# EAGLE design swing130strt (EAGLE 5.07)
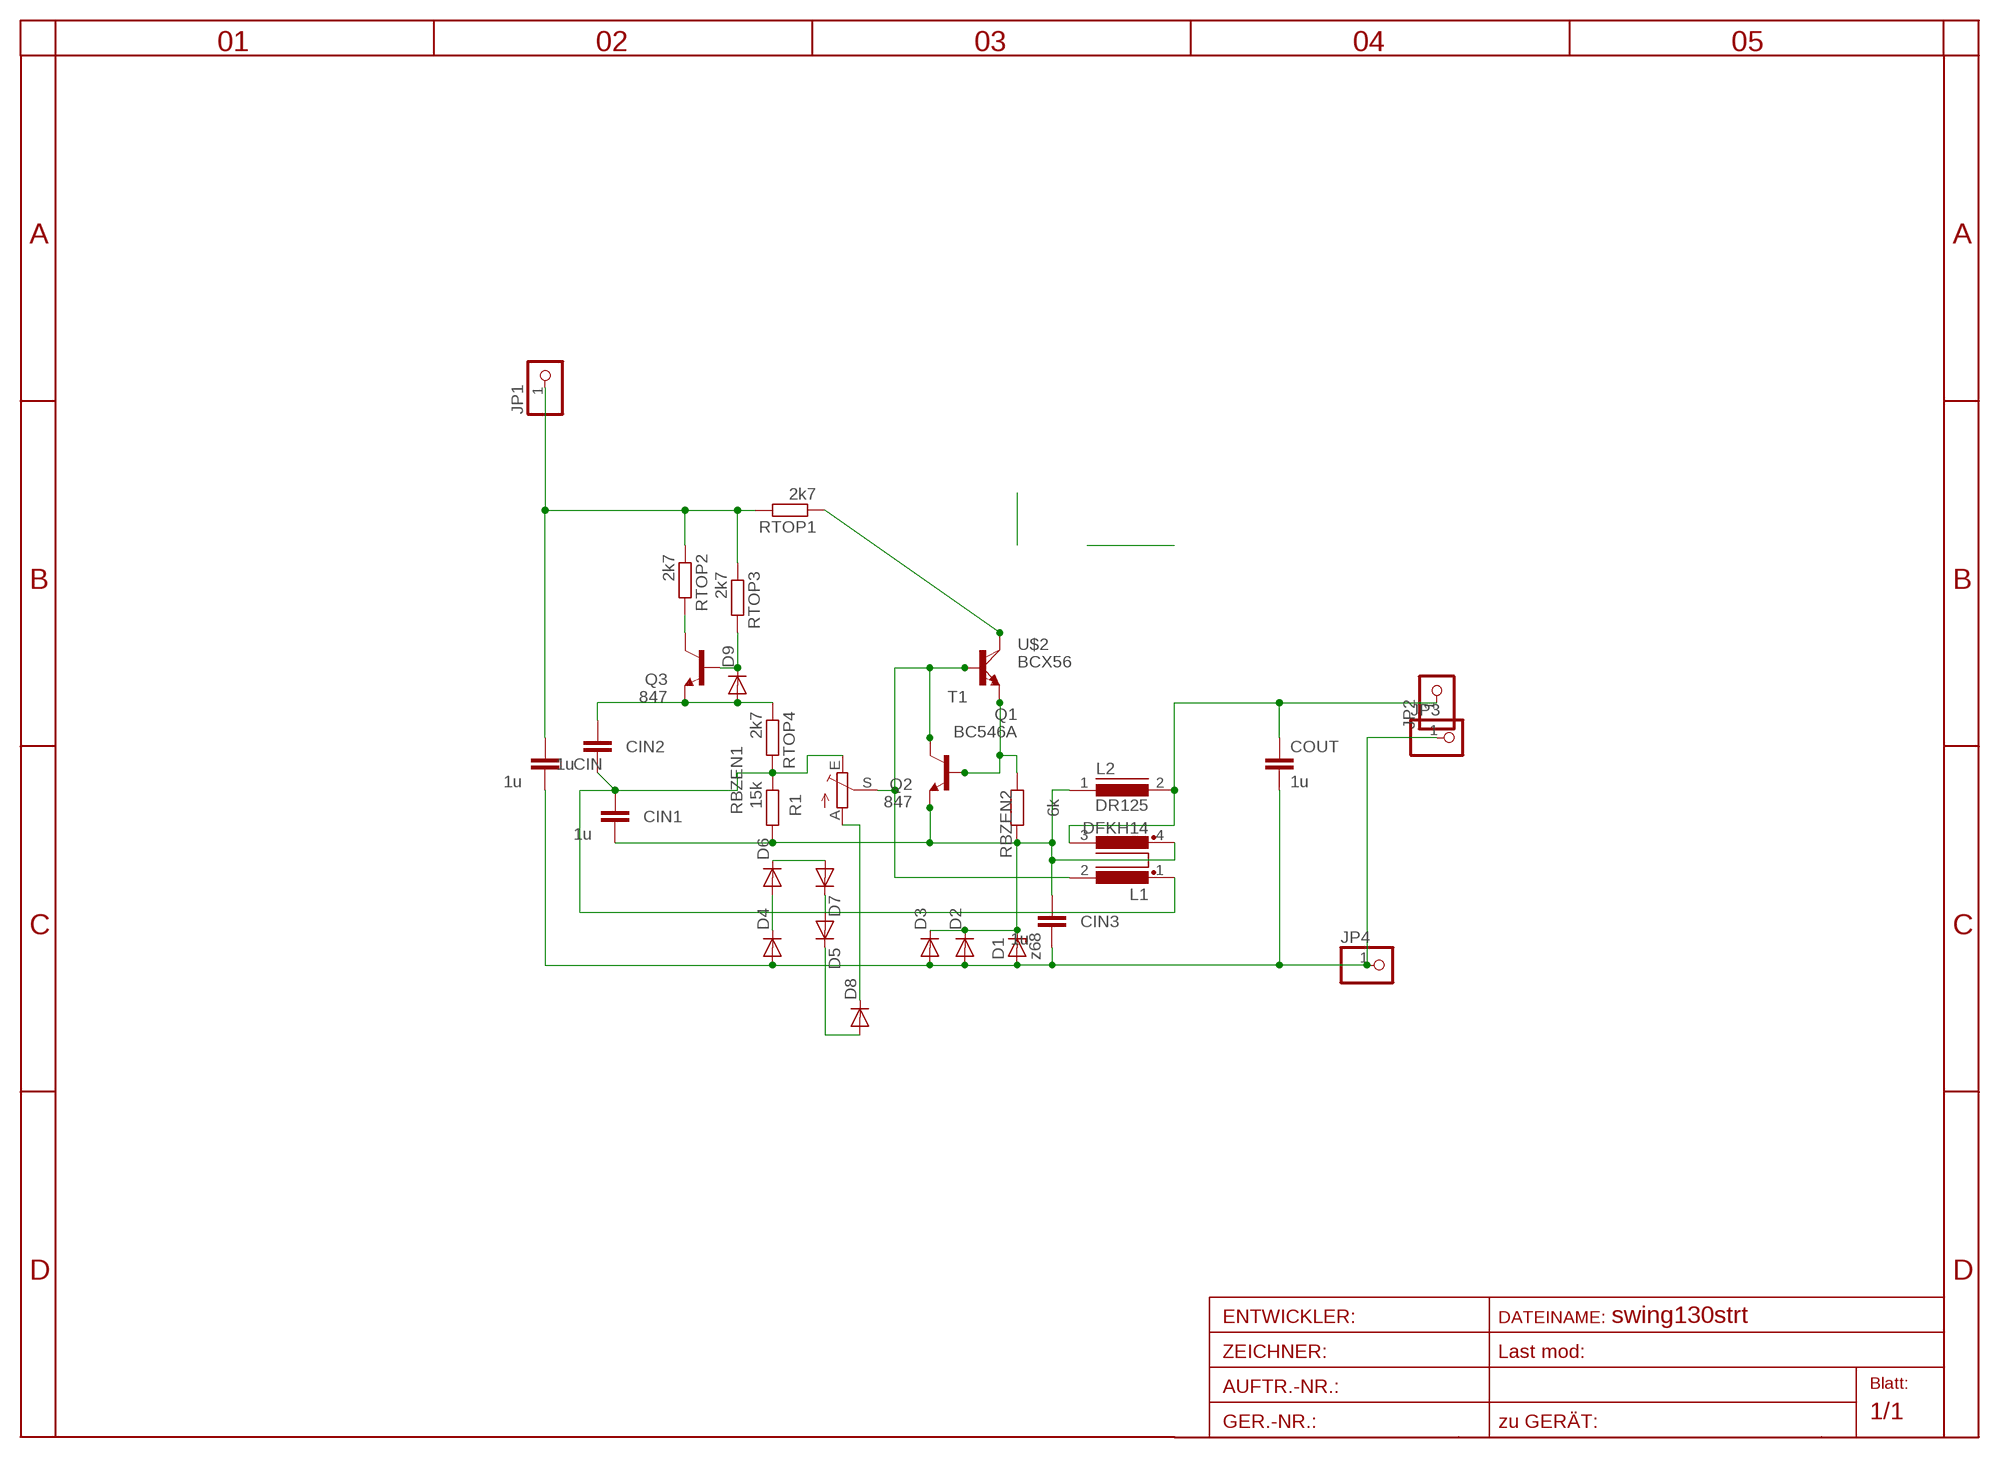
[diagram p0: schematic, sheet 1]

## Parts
CIN  1u  C-EU025-024X044  [C025-024X044]
CIN1  1u  C-EU025-024X044  [C025-024X044]
CIN2  1u  C-EU025-024X044  [C025-024X044]
CIN3  1u  C-EU025-024X044  [C025-024X044]
COUT  1u  C-EU025_050-055X075  [C025_050-055X075]
D1  z68  ZENER-DIODESOD80C  [SOD80C]
D2  DIODE-D-5  [D-5]
D3  DIODE-SMC  [SMC]
D4  DIODE-MINIMELF  [MINIMELF]
D5  DIODE-MINIMELF  [MINIMELF]
D6  DIODE-MINIMELF  [MINIMELF]
D7  DIODE-MINIMELF  [MINIMELF]
D8  DIODE-MINIMELF  [MINIMELF]
D9  DIODE-MINIMELF  [MINIMELF]
JP1  PINHD-1X11X0.4  [1X01]
JP2  PINHD-1X11X0.4  [1X01]
JP3  PINHD-1X11X0.4  [1X01]
JP4  PINHD-1X11X0.4  [1X01]
L1  DFKH14  [DFKH14]
L2  DR125  [DR125]
Q1  BC546A  [TO92-EBC]
Q2  847  BC847ASMD  [SOT23]
Q3  847  BC847ASMD  [SOT23]
R1  TRIM_EU-S64W  [S64W]
RBZEN1  15k  R-EU_0204/3  [0204/3]
RBZEN2  6k  R-EU_0207/10  [0207/10]
RTOP1  2k7  R-EU_0207/12  [0207/12]
RTOP2  2k7  R-EU_R0805  [R0805]
RTOP3  2k7  R-EU_R0805  [R0805]
RTOP4  2k7  R-EU_0204/5  [0204/5]
T1  -NPN-TO126V  [TO126V]
U$2  BCX56  [SOT223]

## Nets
C: RTOP1.1 T1.2(C) U$2.2(C)
CB: L1.2 Q1.C Q2.3(C) R1.S T1.3(B) U$2.1(B)
DB: CIN1.2 CIN3.1 D1.C D2.C D3.C L1.4 L2.1 Q1.E Q2.2(E) RBZEN1.2 RBZEN2.2
EE: Q1.B Q2.1(B) RBZEN2.1 T1.1(E) U$2.3(E)
GND: CIN3.2 CIN.2 COUT.2 D1.A D2.A D3.A D4.A JP3.1 JP4.1
MID: CIN1.1 CIN2.2 L1.1 R1.E RBZEN1.1 RTOP4.2
N$1: D4.C D6.A
N$2: D6.C D7.A
N$4: D5.A D7.C
N$5: D5.C D8.A
N$7: CIN2.1 D9.A Q3.2(E) RTOP4.1
N$8: D8.C R1.A
N$9: D9.C Q3.1(B) RTOP3.2
N$10: Q3.3(C) RTOP2.2
OUT: COUT.1 JP2.1 L1.3 L2.2
VPLUS: CIN.1 JP1.1 RTOP1.2 RTOP2.1 RTOP3.1

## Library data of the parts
CIN CIN1-CIN3 COUT = rcl:C-EU: CAPACITOR, European symbol
D1 = diode:ZENER-DIODE: Z-Diode
D2 = diode:DIODE-: DIODE
D3-D9 = diode-1:DIODE-: DIODE
JP1-JP4 = pinhead:PINHD-1X1: PIN HEADER
L1 = inductors:DFKH14: FILTER
L2 = inductors:DR125: High Power Density, High Efficiency, Shielded Inductors
Q1 = transistor-npn:BC546*: NPN Transistor
Q2 Q3 = transistor-npn:BC847*: NPN Transistor
R1 = pot-7:TRIM_EU-: POTENTIOMETER
RBZEN1 RBZEN2 RTOP1-RTOP4 = rcl:R-EU_: RESISTOR, European symbol
T1 = transistor:*-NPN-: NPN Transistror BF959 corrected 2008.03.06
U$2 = transistor-power:BCX56

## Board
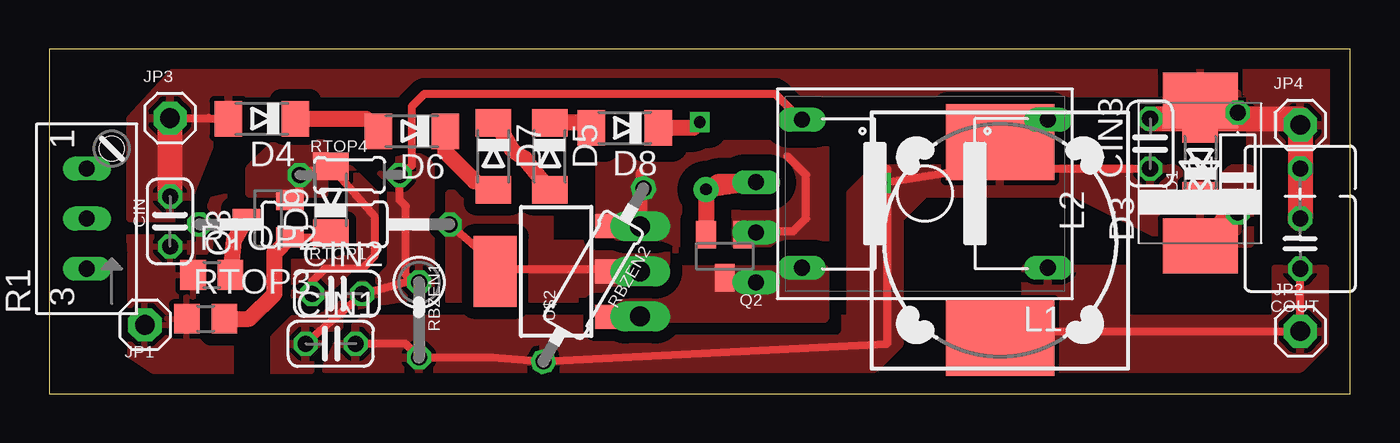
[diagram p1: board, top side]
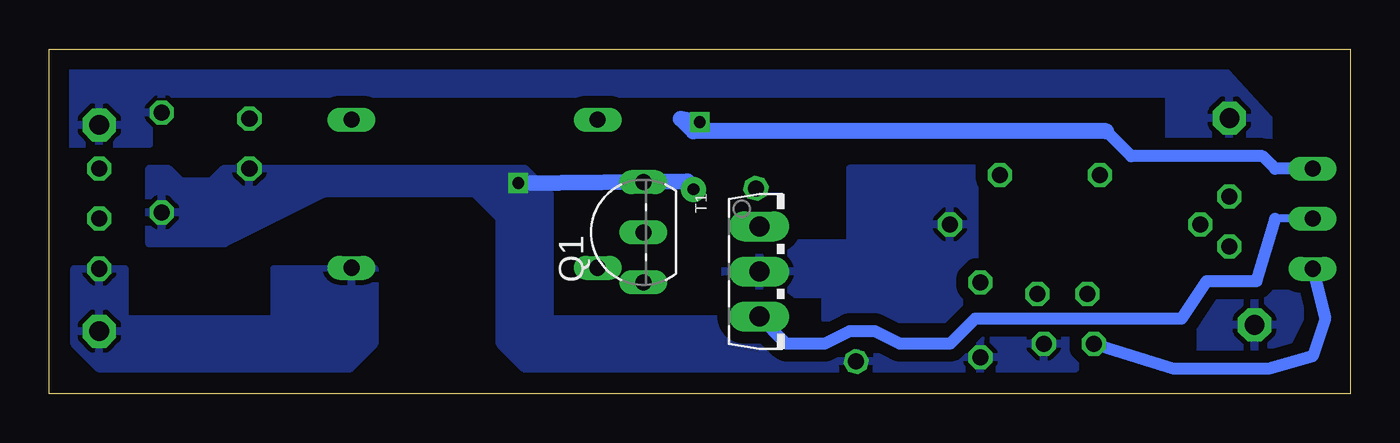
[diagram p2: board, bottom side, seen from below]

Size 66.04 x 17.5 mm. Coordinates in mm from the lower left corner, seen from the top.
Outline: 0,0 66.04,0 66.04,17.5 0,17.5 0,0
Copper layers (1*16): Top 0.035mm / dielectric 1.5mm / Bottom 0.035mm
Design rules "default *": minimum track width 10mil, minimum drill 20mil, track to track 8mil, track to pad 8mil, pad to pad 8mil, via to via 8mil, smd to smd 8mil, copper to edge 40mil, drill to drill 8mil, minimum pad ring 1mil, minimum via ring 8mil, stop-mask expansion 4mil, vias tented up to drill 0mil, thermal gap 10mil

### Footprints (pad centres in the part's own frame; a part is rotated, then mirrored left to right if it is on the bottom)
C025-024X044 = drill 0.813 octagon: 1 -1.27,0; 2 1.27,0
C025_050-055X075 = drill 0.813 octagon: 1 -1.27,0; 2 1.27,0; 3 3.81,0
SOD80C = smd 1.4 x 1.8: A 1.7,0; C -1.7,0
D-5 = drill 0.813 octagon: A 2.54,0; C -2.54,0
SMC = smd 2.8 x 3.8: A 3.7,0; C -3.7,0
MINIMELF = smd 1.4 x 1.8: A 1.7,0; C -1.7,0
1X01 = drill 1 pad 1.676 octagon: 1 0,0
DFKH14 = drill 0.813 long: 1 6.248,-3.759; 2 6.248,3.759; 3 -6.248,3.759; 4 -6.248,-3.759
DR125 = smd 3.85 x 5.5: 1 -4.975,0; 2 4.975,0
TO92-EBC = drill 0.813 long: B 0,-1.27; C -2.54,-1.27; E 2.54,-1.27
SOT23 = smd 1 x 1.4: 1 -0.95,-1.1; 2 0.95,-1.1; 3 0,1.1
S64W = drill 0.813 long: A 2.54,1.27; E -2.54,1.27; S 0,1.27
0204/3 = drill 0.813 octagon: 1 -1.27,0; 2 2.54,0
0207/10 = drill 0.813 octagon: 1 -5.08,0; 2 5.08,0
0207/12 = drill 0.813 octagon: 1 -6.35,0; 2 6.35,0
R0805 = smd 1.3 x 1.5: 1 -0.95,0; 2 0.95,0
0204/5 = drill 0.813 octagon: 1 -2.54,0; 2 2.54,0
TO126V = drill 1.016 long: 1 -2.286,-1.27; 2 0,-1.27; 3 2.286,-1.27
SOT223 = smd 1.219 x 2.235: 1 -2.311,-3.099; 2 0,-3.099; 3 2.311,-3.099 | smd 3.6 x 2.2: 4 0,3.099

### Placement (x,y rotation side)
CIN  6.13,8.75 90 top
CIN1  14.29,2.54 0 top
CIN2  14.61,5.08 0 top
CIN3  55.88,12.7 90 top
COUT  63.5,7.62 90 top
D1  58.42,11.75 90 top
D2  60.32,11.75 90 top
D3  58.42,11.2 90 top
D4  10.79,13.97 180 top
D5  25.4,12.06 270 top
D6  18.41,13.34 180 top
D7  22.54,12.06 270 top
D8  29.21,13.5 180 top
D9  14.29,9.84 90 top
JP1  4.86,3.5 0 top
JP2  63.5,3.17 0 top
JP3  6.13,14 0 top
JP4  63.5,13.65 0 top
L1  44.45,10.16 180 top
L2  48.26,7.8 270 top
Q1  37.15,8.2 90 bottom
Q2  34.29,6.99 180 top
Q3  11.11,8.89 90 top
R1  3.17,8.89 90 top
RBZEN1  18.77,4.38 270 top
RBZEN2  27.62,6.03 240 top
RTOP1  13.97,8.6 180 top
RTOP2  8.26,6.03 0 top
RTOP3  7.94,3.81 0 top
RTOP4  15.24,11.11 0 top
T1  28.73,6.21 270 bottom
U$2  25.73,6.21 90 top

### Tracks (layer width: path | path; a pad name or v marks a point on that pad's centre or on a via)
C
  Top 0.406: RTOP1.1 22.54,6.67 22.86,6.35 28.69,6.35 U$2.2 T1.2
  pour Bottom (isolate 0.61): 19.05,11.43 25.4,11.43 25.4,7.62 31.75,7.62 31.75,5.08 26.67,5.08 26.67,3.81 19.05,3.81
  pour Top (isolate 0.61, rank 4, no thermals): 20.32,10.16 25.4,10.16 25.4,7.62 31.75,7.62 31.75,5.08 26.67,5.08 26.67,3.81 20.32,3.81
CB
  Bottom 0.406: R1.S 3.81,8.89
  Bottom 0.61: 3.81,8.89 4.76,5.71 7.3,5.71 8.57,3.81 19.05,3.81 20.32,2.54 22.86,2.54 24.13,3.17 25.4,3.17 26.67,2.54 28.62,2.54 T1.3
  pour Top (isolate 0.61, rank 2, no thermals): 39.37,6.35 39.37,3.81 27.94,3.81 31.75,6.35
DB  (via drill 0.6, 0.6 pad 1.27)
  Top 0.406: 46.88,11.43 CIN3.1 | 46.88,11.43 L2.1 | CIN1.2 18.08,2.54 RBZEN1.2 22.48,1.84 RBZEN2.2 42.54,2.54 42.54,11.43 v42.23,10.7 46.88,11.43 | Q2.2
  Top 0.813: v33.34,10.38 Q1.E 33.92,10.74 33.34,10.16 Q2.2 | L2.1 49.55,12.77 L1.4 | D2.C 59.9,9.21 D3.C
  Bottom 0.813: v42.23,10.7 33.66,10.79 33.34,10.48 v33.34,10.38
  pour Top (isolate 0.61, rank 3): 15.24,3.81 13.97,1.27 41.91,1.27 43.18,2.54 43.18,8.89 44.45,10.16 52.07,10.16 57.15,7.62 60.96,7.62 60.96,11.43 60.01,11.43 59.37,10.79 57.78,10.79 57.15,11.43 41.91,11.43 40.64,10.16 40.64,3.81
  pour Bottom (isolate 0.61, rank 3): 13.97,3.81 13.97,1.27 41.91,1.27 43.18,2.54 43.18,8.89 44.45,10.16 52.07,10.16 57.15,7.62 60.96,7.62 60.96,11.43 60.01,11.43 59.37,10.79 57.78,10.79 57.15,11.43 41.91,11.43 40.64,10.16 40.64,3.81
EE
  Top 0.406: RBZEN2.1 30.16,8.78 U$2.3 29.98,8.52 T1.1 30,11.27 | 37.46,12.06 38.42,11.11 38.42,8.89 37.78,8.26 35.41,8.26 Q2.1
  Top 0.813: Q2.1 35.76,8.09 Q1.B
  pour Top (isolate 0.813, rank 4, no thermals): 27.94,8.89 27.94,12.7 28.57,12.06 30.8,12.06 31.43,12.7 39.37,12.7 39.37,7.62 29.21,7.62
GND
  Top 0.406: 63.5,13.97 JP4.1 63.5,13.34 | 58.62,13.97 D1.A | D1.A 59.48,13.97 | D1.A 59.8,13.77 D2.A | JP3.1 8.11,14 D4.A
  Top 0.813: 58.62,13.97 58.62,15.34 D3.A
  Top 1.27: 63.5,13.34 COUT.2 | CIN.2 JP3.1 | CIN3.2 58.62,13.97 | 59.48,13.97 63.5,13.97
  pour Bottom (isolate 0.61): 4.13,13.97 7.62,17.78 66.04,17.78 66.04,12.7 60.96,12.7 60.96,15.24 9.21,15.24 9.21,12.7 4.13,12.7
  pour Top (isolate 0.61): 4.13,13.97 7.62,17.78 66.04,17.78 66.04,12.7 60.96,12.7 60.96,15.24 9.21,15.24 6.67,8.89 4.13,8.89
MID
  Top 0.406: CIN1.1 13.34,2.86 15.56,4.76 CIN2.2 18.2,5.71 RBZEN1.1 18.1,6.01 18.1,9.53 17.78,9.84 RTOP4.2 18.41,11.58 18.41,14.61 19.05,15.24 36.83,15.24 38.1,13.97 38.15,13.97 L1.1
  Bottom 0.61: R1.E 1.27,3.81 1.91,1.91 4.13,1.27 8.94,1.27 CIN1.1
  pour Top (isolate 0.406, rank 4): 16.83,11.75 18.73,12.06 19.37,11.75 19.37,5.08 15.56,4.45 14.92,3.81 14.92,2.86 13.02,0.95 11.43,0.95 11.43,2.86 12.38,3.81 13.65,3.81 15.88,6.03 16.19,6.03 17.14,6.35
N$1
  Top 0.406: 16.08,13.97 D6.A
  Top 0.813: D4.C 16.08,13.97
N$2
  Top 0.406: 21.59,10.79 22.43,10.79 D7.A
  Top 0.813: D6.C 20.11,12.27 21.59,10.79
N$4
  Top 0.406: D7.C 22.54,13.97
  Top 0.813: 22.54,13.97 23.5,12.38 24.13,11.95 D5.A
N$5
  Top 0.406: D8.A 27.4,13.77
  Top 0.813: 27.4,13.77 D5.C
N$7
  Top 0.406: CIN2.1 13.34,5.71 13.97,6.35 15.88,6.35 16.51,6.99 16.51,9 D9.A 12.81,11.22 RTOP4.1 12.7,10.33 Q3.2
  pour Top (isolate 0.406, no thermals): 13.97,12.7 11.43,12.7 10.16,11.43 10.16,10.16 13.97,10.16
  pour Top (isolate 0.406, rank 2): 13.97,11.43 15.24,11.43 16.51,10.16 16.51,6.99 15.88,6.35 15.24,6.35 13.65,4.76 12.38,4.76 12.38,6.67 14.29,6.67 15.24,6.99 15.24,10.79
N$8  (via drill 0.6)
  Top 0.406: v33.02,13.8 32.7,13.5
  Top 0.813: 32.7,13.5 D8.C
  Bottom 0.61: R1.A 3.81,11.43 4.45,12.06 11.11,12.06 12.38,13.34
  Bottom 0.813: 12.38,13.34 33.34,13.34 33.97,13.97 v33.02,13.8
N$9
  Top 0.406: Q3.1 14.17,7.94 D9.C
  Top 0.813: RTOP3.2 10.16,3.81 11.43,5.08 11.43,7.16 Q3.1
N$10
  Top 0.813: Q3.3 9.38,7.79 RTOP2.2
OUT
  Top 0.406: 50.8,3.17 47.41,2.86 L2.2 | 50.8,3.17 JP2.1 COUT.1 | 46.89,3.28 50.8,3.17
  pour Top (isolate 0.61, rank 3): 49.53,6.35 49.53,2.54 50.8,1.27 63.5,1.27 64.77,2.54 64.77,6.35 62.23,6.35 62.23,3.81 54.61,3.81 54.61,6.35
  pour Bottom (isolate 0.61, rank 3): 49.53,6.35 49.53,2.54 50.8,1.27 63.5,1.27 64.77,2.54 64.77,6.35 62.23,6.35 62.23,3.81 54.61,3.81 54.61,6.35
VPLUS
  pour Top (isolate 0.61, rank 2): 9.53,10.16 9.21,6.35 9.21,0.64 6.03,0.64 4.13,1.91 4.13,6.99 4.07,8.26 5.34,9.21
  pour Bottom (isolate 0.61, rank 2): 2.54,3.81 2.54,5.08 7.62,5.08 7.62,1.27 3.81,1.27

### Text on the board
tStop: MICHAEL5.net
bStop: MICHAEL5.net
